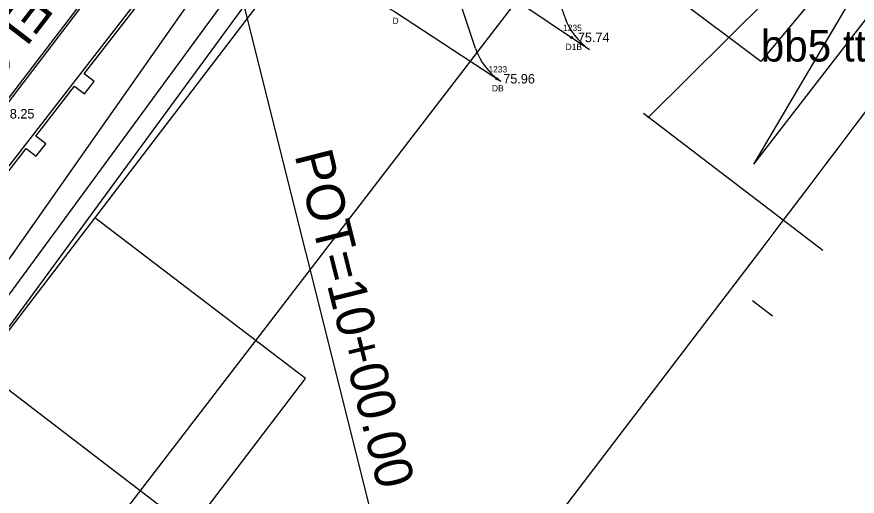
# Model space of a CAD drawing. Extents: x 2500794 to 2511032, y 910653 to 917533.
# Drawn here: x 2506204.2 to 2506337.4, y 913949.2 to 914025.2 of the extents above; entities that cross this region are included whole.
import ezdxf

# ---------------------------------------------------------------- set-up
doc = ezdxf.new("R2010")
doc.units = 0
for name, color, linetype in [('Default', 7, 'Continuous'), ('RD_EX_Driveway', 7, 'Continuous'), ('RD_EX_Driveway_txCode', 7, 'Continuous'), ('RD_EX_H2O_WetLd', 7, 'Continuous'), ('RD_EX_Road', 7, 'Continuous'), ('RD_EX_RW', 7, 'Continuous'), ('RD_EX_TX_Driveway_ELEV', 7, 'Continuous'), ('RD_EX_TX_Road_ELEV', 7, 'Continuous'), ('RD_EX_VEG', 7, 'Continuous'), ('RD_HC_Data', 7, 'Continuous'), ('RD_HC_Data_Rel', 7, 'Continuous'), ('RD_PD_ALT1_TrvlWay', 7, 'Continuous'), ('RD_PD_CstnLmt', 7, 'Continuous'), ('RD_PD_GR', 7, 'Continuous'), ('RD_PD_PaintMed', 7, 'Continuous'), ('RD_PD_RW', 7, 'Continuous'), ('RD_PD_Signals', 7, 'Continuous'), ('RD_Sketch9', 7, 'Continuous'), ('RD_SMD_Locator', 7, 'Continuous'), ('RD_XS_NPDES', 7, 'Continuous')]:
    doc.layers.add(name, color=color, linetype=linetype)

# ---------------------------------------------------------------- blocks, each defined once
blk = doc.blocks.new('POINT_DISPLAY')
at = {"layer": 'Default'}
blk.add_line((0, 0), (0, 0), dxfattribs=at)
blk = doc.blocks.new('Wetlands')
at = {"layer": 'Default'}
blk.add_lwpolyline([(636625.412, 232168.429), (636615.152, 232171.786), (636605.825, 232160.599), (636598.773, 232165.894), (636604.282, 232175.492), (636611.74, 232182.855), (636615.732, 232178.989), (636630.357, 232174.679)], close=True, dxfattribs=at)

msp = doc.modelspace()

# ---------------------------------------------------------------- linework, layer by layer
at = {"layer": 'RD_EX_Driveway'}
for points in [[(2506238.19, 914058.36), (2506269.11, 914037.41), (2506294.99, 914020.02)], [(2506228.78, 914046.14), (2506264.09, 914026.05), (2506280.93, 914014.98)]]:
    msp.add_lwpolyline(points, dxfattribs=at)
at = {"layer": 'RD_EX_Road'}
msp.add_lwpolyline([(2506132.31, 913920.14), (2506200.99, 914009.83), (2506228.78, 914046.14), (2506238.19, 914058.36), (2506261.83, 914089.97), (2506324.5, 914172.22), (2506382.84, 914247.97), (2506424.88, 914303.73), (2506446.4, 914331.89), (2506508.34, 914413.09), (2506571.21, 914495.53), (2506633.01, 914576.81), (2506694.83, 914657.95), (2506756.78, 914739.18)], dxfattribs=at)
at = {"layer": 'RD_EX_RW'}
for p, q in [((2506198.38, 913969.53), (2506826.41, 914790.99)), ((2506231.75, 913944.02), (2506198.38, 913969.53))]:
    msp.add_line(p, q, dxfattribs=at)
at = {"layer": 'RD_EX_VEG'}
msp.add_line((2506205.52, 913926.29), (2506806.36, 914708.13), dxfattribs=at)
at = {"layer": 'RD_HC_Data'}
msp.add_line((2506230.5, 914065.87), (2506260.14, 913947.45), dxfattribs=at)
at = {"layer": 'RD_PD_ALT1_TrvlWay'}
for p, q in [((2506162.95, 913959.41), (2506387.41, 914253)), ((2506291.08, 914025.18), (2506281.52, 914054)), ((2506276.93, 914020.2), (2506268.54, 914045.5))]:
    msp.add_line(p, q, dxfattribs=at)
for centre, end in [((2506300.57, 914028.32), 236.1031), ((2506286.42, 914023.34), 236.6958)]:
    msp.add_arc(centre, 10, 198.3373, end, dxfattribs=at)
at = {"layer": 'RD_PD_CstnLmt'}
msp.add_line((2506249.07, 914044.07), (2506189.92, 913963.41), dxfattribs=at)
at = {"layer": 'RD_PD_GR'}
for p, q in [((2506227.23, 914032.89), (2506190.13, 913985.08)), ((2506214.89, 914016.18), (2506223.96, 914027.88)), ((2506216.47, 914014.95), (2506214.89, 914016.18)), ((2506207.22, 914006.31), (2506213.35, 914014.21)), ((2506213.35, 914014.21), (2506214.94, 914012.98)), ((2506214.94, 914012.98), (2506216.47, 914014.95)), ((2506208.81, 914005.08), (2506207.22, 914006.31)), ((2506207.28, 914003.1), (2506208.81, 914005.08)), ((2506199.56, 913996.43), (2506205.69, 914004.33)), ((2506205.69, 914004.33), (2506207.28, 914003.1))]:
    msp.add_line(p, q, dxfattribs=at)
at = {"layer": 'RD_PD_PaintMed'}
for p, q in [((2506436.97, 914140.76), (2506304.24, 914009.19)), ((2506321.03, 914001.85), (2506417.02, 914125.97)), ((2506321.03, 914001.85), (2506357.86, 914064.15)), ((2506331.97, 913988.16), (2506303.57, 914009.88)), ((2506324, 913977.75), (2506320.82, 913980.18))]:
    msp.add_line(p, q, dxfattribs=at)
at = {"layer": 'RD_PD_RW'}
for p, q in [((2506249.97, 913967.86), (2506216.6, 913993.37)), ((2506231.75, 913944.02), (2506249.97, 913967.86))]:
    msp.add_line(p, q, dxfattribs=at)
at = {"layer": 'RD_PD_Signals'}
msp.add_line((2506187.75, 913965.07), (2506245.23, 914047), dxfattribs=at)
at = {"layer": 'RD_Sketch9'}
msp.add_line((2505975.42, 913534.66), (2506308.52, 913970.35), dxfattribs=at)
msp.add_arc((2498701.92, 919785.88), 9575, 322.600707, 325.616274, dxfattribs=at)
at = {"layer": 'RD_SMD_Locator'}
for centre in [(2506292.15, 914021.93), (2506280.32, 914015.38)]:
    msp.add_circle(centre, 0.15, dxfattribs=at)
at = {"layer": 'RD_XS_NPDES'}
msp.add_line((2506251.49, 914042.29), (2506192.34, 913961.64), dxfattribs=at)

# ---------------------------------------------------------------- block references
at = {"layer": 'Default', "xscale": 3.937007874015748, "yscale": 3.937007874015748}
for name, p in [('Wetlands', (0, 0)), ('POINT_DISPLAY', (2506322.15, 914018.11)), ('POINT_DISPLAY', (2506322.15, 914018.11))]:
    msp.add_blockref(name, p, dxfattribs=at)
at = {"layer": 'RD_EX_H2O_WetLd', "xscale": 3.937007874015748, "yscale": 3.937007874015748}
msp.add_blockref('Wetlands', (0, 0), dxfattribs=at)

# ---------------------------------------------------------------- texts
at = {"layer": 'Default'}
msp.add_text('bb5 tt bb1', height=5, dxfattribs=at).set_placement((2506322.15, 914018.11))
msp.add_text('bb5 tt bb1', height=5, dxfattribs=at).set_placement((2506322.15, 914018.11))
at = {"layer": 'RD_EX_Driveway_txCode'}
for s, p in [('D', (2506263.78, 914024.05)), ('1235', (2506290.81, 914022.93)), ('D1B', (2506291.21, 914019.93)), ('1233', (2506278.97, 914016.38)), ('DB', (2506279.54, 914013.38))]:
    msp.add_text(s, height=1, dxfattribs=at).set_placement(p)
at = {"layer": 'RD_EX_TX_Driveway_ELEV'}
for s, p in [('75.74', (2506293.15, 914021.18)), ('75.96', (2506281.32, 914014.63))]:
    msp.add_text(s, height=1.5, dxfattribs=at).set_placement(p)
at = {"layer": 'RD_EX_TX_Road_ELEV'}
msp.add_text('78.25', height=1.5, dxfattribs=at).set_placement((2506201.99, 914009.08))
at = {"layer": 'RD_HC_Data'}
msp.add_text('POT=10+00.00', height=6, rotation=284.0539, dxfattribs=at).set_placement((2506248.22, 914003.3))
at = {"layer": 'RD_HC_Data_Rel'}
msp.add_text('RELOC. POT=10+00.00', height=6, rotation=232.6007, dxfattribs=at).set_placement((2506209.03, 914034.5))

doc.saveas('drawing.dxf')
